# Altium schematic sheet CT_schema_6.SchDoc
size 254 x 194 mm
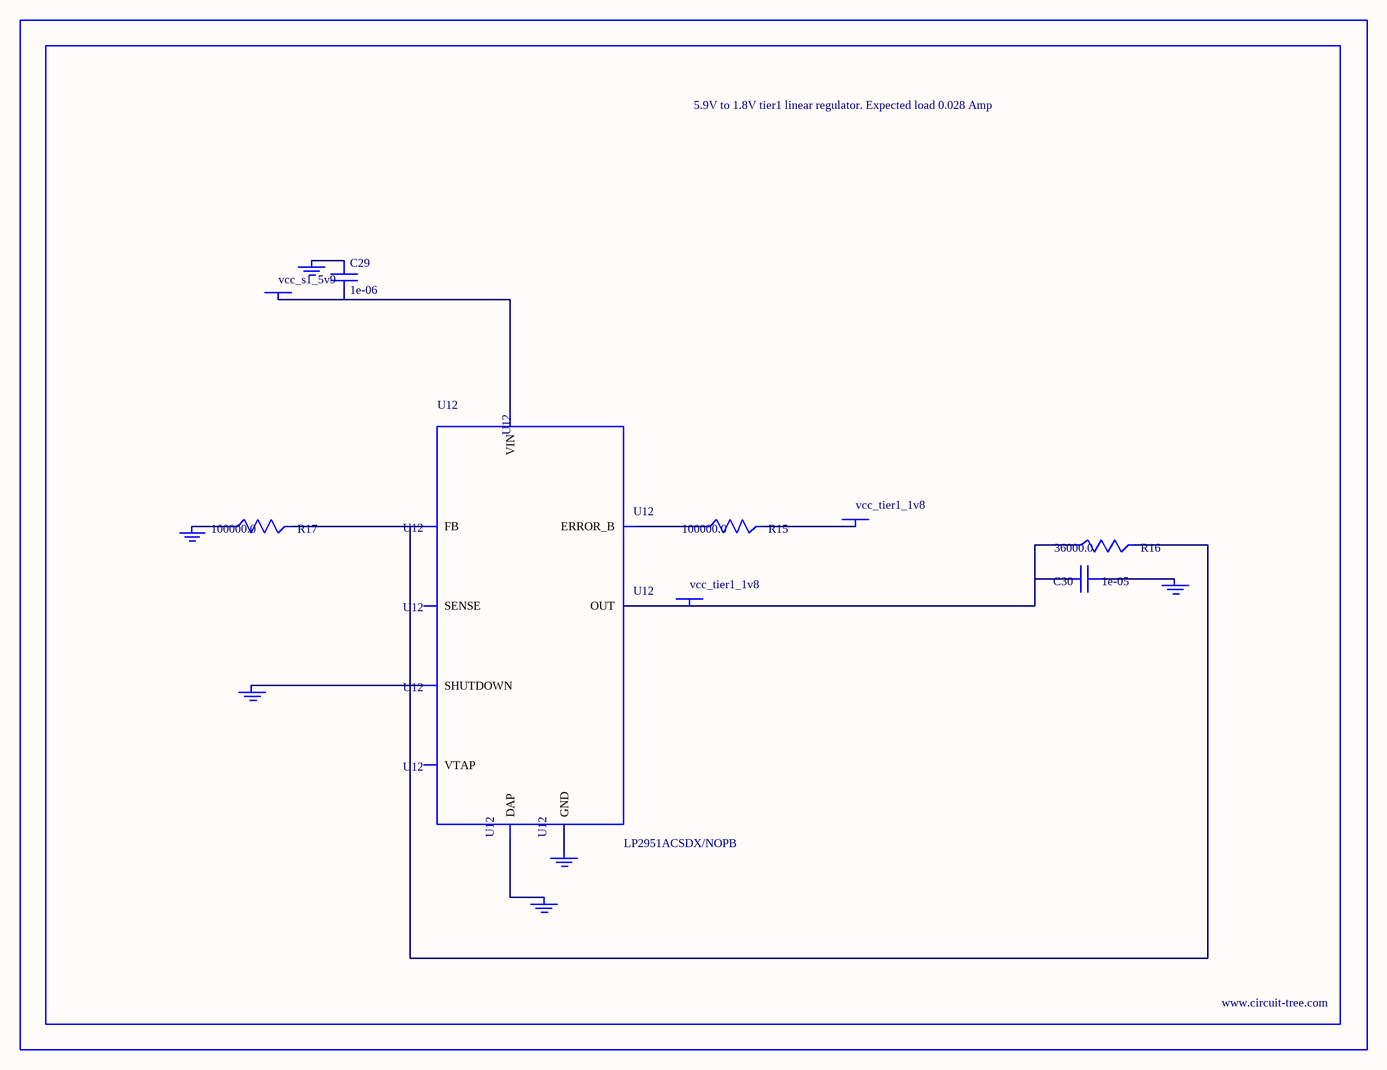
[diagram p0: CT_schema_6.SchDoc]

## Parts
BORDER5  (no value)
C29  1e-06  [C0603]
C30  1e-05  [C0805]
GND_INSTANCE_5_0  (no value)
GND_INSTANCE_5_1  (no value)
GND_INSTANCE_5_2  (no value)
GND_INSTANCE_5_3  (no value)
GND_INSTANCE_5_4  (no value)
GND_INSTANCE_5_5  (no value)
POWER_INSTANCE_5_0  vcc_tier1_1v8
POWER_INSTANCE_5_1  vcc_s1_5v9
POWER_INSTANCE_5_2  vcc_tier1_1v8
R15  100000.0  [R0603]
R16  36000.0  [R0603]
R17  100000.0  [R0603]
U12  LP2951ACSDX/NOPB  [WSON-8]

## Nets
NetC29_1: C29.1 GND_INSTANCE_5_3.0(GND)
NetC29_2: C29.2 POWER_INSTANCE_5_1.0(PWR) U12.8(VIN)
NetC30_1: C30.1 GND_INSTANCE_5_0.0(GND)
NetC30_2: C30.2 POWER_INSTANCE_5_2.0(PWR) R16.1 U12.1(OUT)
NetGND_INSTANCE_5_1_0: GND_INSTANCE_5_1.0(GND) U12.3(SHUTDOWN)
NetGND_INSTANCE_5_2_0: GND_INSTANCE_5_2.0(GND) R17.1
NetGND_INSTANCE_5_4_0: GND_INSTANCE_5_4.0(GND) U12.PAD(DAP)
NetGND_INSTANCE_5_5_0: GND_INSTANCE_5_5.0(GND) U12.4(GND)
NetPOWER_INSTANCE_5_0_0: POWER_INSTANCE_5_0.0(PWR) R15.2
NetR15_1: R15.1 U12.5(ERROR_B)
NetR16_2: R16.2 R17.2 U12.7(FB)

Not connected (* = marked no-connect by the designer): U12 2(SENSE) 6(VTAP)

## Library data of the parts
BORDER5 = BORDER_PAGE5
C29 = C0603C105K3RACTU
C30 = GRM219R60J106ME19D
GND_INSTANCE_5_0-GND_INSTANCE_5_5 = GND
POWER_INSTANCE_5_0-POWER_INSTANCE_5_2 = PWR
R15 R17 = RC0603JR-07100KL
R16 = RC0603JR-0736KL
